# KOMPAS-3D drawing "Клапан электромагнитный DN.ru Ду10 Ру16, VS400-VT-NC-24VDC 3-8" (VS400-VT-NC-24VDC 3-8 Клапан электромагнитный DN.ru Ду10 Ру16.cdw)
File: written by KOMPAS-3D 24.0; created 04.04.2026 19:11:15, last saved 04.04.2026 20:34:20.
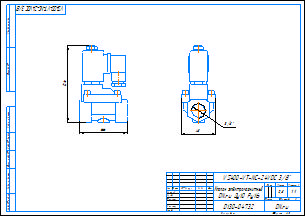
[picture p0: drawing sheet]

Document properties: c3d_UniqueCompID: ef56311e-7521-43dc-8291-0e6108b3d81d; Обозначение: VS400-ET-NC-220VAC 3-8; Наименование: Клапан электромагнитный DN.ru Ду10 Ру16; Автор: artio; Класс точности: c; Знак неуказанной шероховатости: Шероховатость не задана; Рассекать на разрезах: Да; Автор: artio; Форматы листов документа: A3; Полное имя файла: VS400-VT-NC-24VDC 3-8 Клапан электромагнитный DN.ru Ду10 Ру16.m3d; Масса: 0.797; Наименование: Клапан электромагнитный DN.ru Ду10 Ру16; Количество листов документа: 1; Примечание: D130-04732

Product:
- Body: Тело 1  | qty 1
    Масса: 1.030062
- Part/product: Клапан электромагнитный DN.ru Ду10 Ру16  | designation VS400-VT-NC-24VDC 3-8
    Масса: 0.797
    Раздел спецификации: Прочие изделия
    Примечание: D130-04732
    additional columns: ef56311e-7521-43dc-8291-0e6108b3d81d; VS400-ET-NC-220VAC 3-8; artio; c; Шероховатость не задана; Да

Views: Вид 1, Спереди, Проекционный вид 2
Referenced files in C:\Users\artio\OneDrive\Рабочий стол\Клапан электромагнитный DN.ru\VS400-ET-NC\VS400-ET-NC-24VDC\: VS400-ET-NC-24VDC 3-8 Клапан электромагнитный DN.ru Ду10 Ру16.m3d
Referenced files in C:\Users\artio\OneDrive\Рабочий стол\Клапан электромагнитный DN.ru\VS400-VT-NC\VS400-VT-NC-24VDC\: VS400-VT-NC-24VDC 3-8 Клапан электромагнитный DN.ru Ду10 Ру16.m3d, VS400-VT-NC-24VDC 3-8 Клапан электромагнитный DN.ru Ду10 Ру16.cdw
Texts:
  VS400-VT-NC-24VDC 3-8
  Клапан электромагнитный
  DN.ru Ду10 Ру16
  VS400-VT-NC-24VDC 3/8"
  VS400-VT-NC-24VDC 3/8"-
  Клапан электромагнитный DN.ru Ду10 Ру16
  VS400-VT-NC-24VDC 3-8 Клапан электромагнитный DN.ru Ду10 Ру16
Dimensions and other numbers on the sheet: 0; 3; 2; 4; 48; 3/8"; 66; 106; 1:1; 1; 0,8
